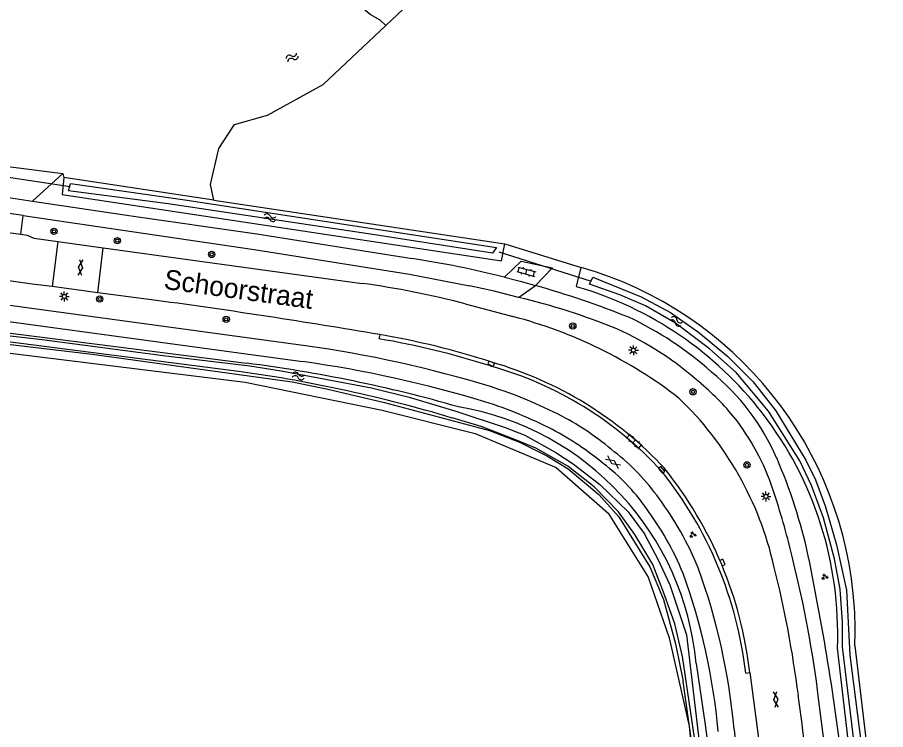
# Model space of a CAD drawing. Extents: x 134297 to 137000, y 403500 to 406000.
# Drawn here: x 136614.5 to 136724.4, y 404031.9 to 404122.1 of the extents above; entities that cross this region are included whole.
import ezdxf

# ---------------------------------------------------------------- set-up
doc = ezdxf.new("R2010")
doc.units = 0
for name, color, linetype in [('gg-anno-openbare ruimte label', 7, 'Continuous'), ('gg-knt-bronhoudergrens', 7, 'Continuous'), ('gg-knt-verharding', 7, 'Continuous'), ('gg-kntw-bovenkant insteek waterloop', 7, 'Continuous'), ('gg-kntw-waterlijn', 7, 'Continuous'), ('gg-kwrk-duiker nz buis', 7, 'Continuous'), ('gt-grn-groengrens', 7, 'Continuous'), ('gt-grn-weggrens', 7, 'Continuous'), ('gt-symb-boom', 7, 'Continuous'), ('gt-symb-gesloten verharding', 7, 'Continuous'), ('gt-symb-groenvak', 7, 'Continuous'), ('gt-symb-klinker verharding', 7, 'Continuous'), ('gt-symb-kolk', 7, 'Continuous'), ('gt-symb-lichtmast', 7, 'Continuous'), ('gt-symb-watersymbool', 7, 'Continuous')]:
    doc.layers.add(name, color=color, linetype=linetype)

# ---------------------------------------------------------------- blocks, each defined once
blk = doc.blocks.new('gt0-BOOM')
at = {"layer": 'gt-symb-boom'}
for radius in [0.4, 0.2]:
    blk.add_circle((0, 0), radius, dxfattribs=at)
blk = doc.blocks.new('gt0-LMAST')
at = {"layer": 'gt-symb-lichtmast'}
for p, q in [((-0.18, 0.17), (-0.45, 0.44)), ((-0.01, 0.25), (-0.01, 0.62)), ((0.17, 0.17), (0.44, 0.44)), ((-0.26, 0), (-0.63, 0)), ((-0.18, -0.18), (-0.45, -0.45)), ((-0.01, -0.25), (-0.01, -0.63)), ((0.44, -0.45), (0.17, -0.18)), ((0.24, 0), (0.62, 0))]:
    blk.add_line(p, q, dxfattribs=at)
blk.add_circle((-0.01, 0), 0.25, dxfattribs=at)
blk = doc.blocks.new('gt0-GRVAK')
at = {"layer": 'gt-symb-groenvak'}
for p, q in [((-0.11, 0.19), (-0.23, 0.24)), ((-0.18, 0.15), (0.09, 0.15)), ((-0.09, 0.21), (-0.16, 0.32)), ((-0.05, 0.21), (-0.05, 0.39)), ((0, 0.21), (0.06, 0.32)), ((0.01, 0.19), (0.13, 0.24)), ((0.26, -0.05), (0.2, 0.06)), ((0.3, -0.05), (0.3, 0.13)), ((0.35, -0.05), (0.41, 0.06)), ((-0.24, -0.23), (-0.36, -0.18)), ((-0.32, -0.26), (-0.05, -0.26)), ((-0.23, -0.21), (-0.29, -0.09)), ((-0.18, -0.2), (-0.18, -0.02)), ((-0.14, -0.21), (-0.07, -0.09)), ((-0.12, -0.23), (0, -0.18)), ((0.24, -0.07), (0.12, -0.02)), ((0.17, -0.11), (0.44, -0.11)), ((0.37, -0.07), (0.49, -0.02))]:
    blk.add_line(p, q, dxfattribs=at)
blk = doc.blocks.new('gt0-GESVH1')
at = {"layer": 'gt-symb-gesloten verharding'}
for p, q in [((-0.99, -0.26), (0.01, 0.24)), ((0.01, -0.26), (-0.99, 0.24)), ((0.01, 0.24), (1.01, -0.26)), ((1.01, 0.24), (0.01, -0.26))]:
    blk.add_line(p, q, dxfattribs=at)
blk = doc.blocks.new('gt0-KOLK')
at = {"layer": 'gt-symb-kolk'}
blk.add_lwpolyline([(0, 0), (0.38, 0), (0.38, 0.4), (-0.38, 0.4), (-0.38, 0), (0, 0)], dxfattribs=at)
blk = doc.blocks.new('gt0-WA')
at = {"layer": 'gt-symb-watersymbool'}
for centre, start, end in [((-0.32, 0.02), 28.0725, 151.9275), ((0.43, 0.42), 208.0725, 331.9275), ((-0.32, -0.43), 28.0725, 151.9275), ((0.43, -0.03), 208.0725, 331.9275)]:
    blk.add_arc(centre, 0.425, start, end, dxfattribs=at)
blk = doc.blocks.new('gt0-KL1')
at = {"layer": 'gt-symb-klinker verharding'}
for p, q in [((-1.15, 0.3), (1.15, 0.3)), ((-1, -0.3), (-1, 0.3)), ((-0.5, 0.3), (-0.5, 0.45)), ((0, -0.3), (0, 0.3)), ((0.5, 0.3), (0.5, 0.45)), ((1, -0.3), (1, 0.3)), ((-1.15, -0.3), (1.15, -0.3)), ((-0.5, -0.45), (-0.5, -0.3)), ((0.5, -0.45), (0.5, -0.3))]:
    blk.add_line(p, q, dxfattribs=at)

msp = doc.modelspace()

# ---------------------------------------------------------------- linework, layer by layer
at = {"layer": 'gg-knt-bronhoudergrens'}
msp.add_line((136661.12, 404121.02), (136664.77, 404124.47), dxfattribs=at)
for points in [[(136661.12, 404121.02), (136660.4, 404121.69), (136659.13, 404122.43), (136657.01, 404124.23), (136651.93, 404126.77), (136645.8, 404133.12), (136643.89, 404137.78), (136643.04, 404141.91), (136642.75, 404143.92), (136636.98, 404147.84)], [(136639.37, 404098.93), (136638.96, 404100.89), (136640.02, 404105.44), (136641.98, 404108.51), (136646.16, 404109.67), (136653.2, 404113.54), (136661.12, 404121.02)], [(136565.32, 404088.32), (136600.22, 404081.2), (136643.34, 404075.89), (136660.67, 404072.34), (136672.43, 404069.38), (136682.66, 404065.06), (136689.26, 404059.31), (136694.33, 404051.19), (136696.95, 404043.5), (136699.49, 404032.34), (136701.69, 404009.21), (136701.34, 404009.21)]]:
    msp.add_lwpolyline(points, dxfattribs=at)
at = {"layer": 'gg-knt-verharding'}
for p, q in [((136607.31, 404103.94), (136620.25, 404102.31)), ((136616.42, 404098.79), (136620.25, 404102.31)), ((136606.78, 404100.22), (136616.42, 404098.79)), ((136615.26, 404096.96), (136606.36, 404098.26)), ((136614.95, 404094.6), (136615.26, 404096.96)), ((136606.02, 404095.78), (136614.95, 404094.6)), ((136619.62, 404093.68), (136618.9, 404087.97)), ((136619.62, 404093.68), (136625.35, 404092.89)), ((136624.7, 404087.2), (136625.35, 404092.89)), ((136625.35, 404092.89), (136658.13, 404088.38)), ((136650.95, 404080.49), (136599.45, 404087.49)), ((136624.7, 404087.2), (136618.9, 404087.97)), ((136632.12, 404086.22), (136624.7, 404087.2)), ((136660.36, 404081.89), (136660.25, 404081.38)), ((136706.66, 404039.06), (136707.17, 404039.13)), ((136705.19, 404031.9), (136709.48, 403985.12))]:
    msp.add_line(p, q, dxfattribs=at)
for points in [[(136616.42, 404098.79), (136628.91, 404096.94), (136644.81, 404094.67), (136664.47, 404091.53)], [(136615.26, 404096.96), (136644.46, 404092.68), (136664.1, 404089.55), (136671.71, 404088.08)], [(136614.95, 404094.6), (136615.77, 404094.5), (136616.61, 404094.1), (136619.62, 404093.68)], [(136618.9, 404087.97), (136616.39, 404088.3), (136603.65, 404090.09), (136593.07, 404091.67)], [(136676.14, 404089.17), (136678.24, 404091.18), (136682.19, 404090.34), (136680.05, 404088.12)], [(136578.66, 404089.05), (136588.33, 404087.2), (136599.16, 404085.49), (136650.59, 404078.48)], [(136676.14, 404089.17), (136678.1, 404088.66), (136680.05, 404088.12)], [(136677.91, 404086.61), (136674.82, 404087.39), (136671.71, 404088.08)], [(136671.16, 404085.78), (136674.18, 404085), (136677.19, 404084.18)], [(136707.17, 404039.13), (136708.17, 404031.47), (136709.02, 404023.8), (136710.15, 404011.91), (136711.12, 404000), (136711.34, 403997.04), (136711.41, 403995.52)], [(136718.71, 404007.42), (136717.17, 404024.79), (136716.57, 404030.31), (136715.87, 404035.83)]]:
    msp.add_lwpolyline(points, dxfattribs=at)
for centre, radius, start, end in [((136645.52, 403967.49), 125.47, 75.8773, 81.316), ((136642.21, 403974.69), 114.81, 75.3963, 82.0295), ((136645.54, 403967.48), 125.48, 68.3367, 74.0353), ((136658.88, 404005.82), 83, 67.7322, 76.7429), ((136522.97, 403280.07), 813.51, 80.2772, 82.28963), ((136662.32, 404027.32), 58.78, 52.3757, 75.3438), ((136673.23, 404044.58), 43.69, 48.2119, 64.7543), ((136644.19, 403985.87), 97.38, 71.8546, 80.4427), ((136672.84, 404044.1), 42.32, 48.2153, 65.5904), ((136643.08, 403980.31), 102.51, 72.2302, 80.3591), ((136630.2, 403930.91), 151.01, 72.9899, 82.1027), ((136630.08, 403930.44), 149.45, 73.0472, 82.1136), ((136661.89, 404033.35), 46.29, 42.492, 74.3556), ((136661.3, 404032.4), 47.87, 42.8297, 73.967), ((136684.09, 404054.8), 28.86, 23.4717, 50.7778), ((136656.57, 404019.58), 58.51, 62.7099, 72.2815), ((136680.36, 404051.21), 32.02, 38.1141, 49.7819), ((136656.67, 404020), 56.04, 62.8878, 72.3466), ((136668.84, 404043.25), 42.42, 12.7332, 46.2021), ((136665.8, 404038.57), 37.41, 49.6417, 61.9392), ((136680.55, 404052.34), 31.18, 17.4794, 36.6898), ((136665.1, 404037.38), 36.73, 50.1476, 62.2423), ((136673.38, 404045.5), 27.25, 35.0376, 52.3544), ((136673.69, 404045.77), 24.81, 35.045, 52.9511), ((136648.83, 404039.52), 67.29, 12.346, 23.4403), ((136656.86, 404033.34), 50.12, 6.5491, 38.6178), ((136657.31, 404033.48), 50.17, 6.4574, 38.8239), ((136663.58, 404037.22), 40.04, 22.2628, 36.6825), ((136628.27, 404034.28), 86.48, 12.8031, 18.4856), ((136664.06, 404037.53), 37.44, 22.1532, 36.9064), ((136571.75, 404018.2), 145.2, 6.9716, 14.0482), ((136376.88, 403984.88), 344.67, 6.676, 11.553), ((136624.01, 404024.62), 81.5, 5.1267, 19.9256), ((136571.63, 404017.99), 142.85, 7.3457, 14.0202), ((136621.92, 404024.12), 81.61, 5.3152, 19.7199), ((136075.65, 403952.45), 643.14, 4.88308, 7.48781)]:
    msp.add_arc(centre, radius, start, end, dxfattribs=at)
at = {"layer": 'gg-kntw-bovenkant insteek waterloop'}
for p, q in [((136639.37, 404098.93), (136620.4, 404101.8)), ((136639.37, 404098.93), (136676.16, 404093.37)), ((136685.24, 404087.97), (136685.85, 404090.41)), ((136598.99, 404083.97), (136643.49, 404078.28))]:
    msp.add_line(p, q, dxfattribs=at)
for points in [[(136620.4, 404101.8), (136620.19, 404099.64), (136675.74, 404091.22), (136676.16, 404093.37)], [(136565.22, 404089.23), (136571.29, 404087.63), (136581.09, 404085.35), (136586.26, 404084.37), (136593.96, 404083.11), (136601.51, 404082.09), (136623.96, 404079.43), (136649.28, 404075.92), (136653.62, 404075.02), (136660.97, 404073.3), (136674.23, 404069.75), (136678.05, 404068.29), (136681.58, 404066.52), (136684.2, 404064.93), (136688.06, 404061.66), (136690.6, 404058.85), (136694.53, 404052.51), (136696.26, 404048.36), (136697.76, 404042.75), (136698.75, 404038.01)], [(136720.45, 404042.49), (136722.46, 404025.43), (136723.74, 404013.87)], [(136724.35, 404008.35), (136722.15, 404008.09), (136720.26, 404025.16), (136718.26, 404042.23)], [(136700.37, 404040.28), (136701.52, 404032.49), (136702.53, 404024.69), (136703.69, 404012.35), (136704.77, 404000)], [(136702.66, 403999.96), (136701.81, 404009.69), (136700.75, 404021.18), (136699.83, 404030.17), (136698.75, 404038.01)]]:
    msp.add_lwpolyline(points, dxfattribs=at)
for centre, radius, start, end in [((136672.56, 404044.36), 47.93, 3.4685, 73.8961), ((136672.54, 404044.01), 45.75, 37.659, 73.8804), ((136620.6, 403899.28), 180.46, 74.0068, 82.7147), ((136664.25, 404037), 36.27, 5.1881, 80.3547), ((136672.54, 404044.02), 45.75, 357.7552, 37.6557), ((136673.1, 404044.36), 47.39, 357.7421, 3.5079)]:
    msp.add_arc(centre, radius, start, end, dxfattribs=at)
at = {"layer": 'gg-kntw-waterlijn'}
msp.add_line((136642.83, 404077.2), (136598.33, 404082.89), dxfattribs=at)
for points in [[(136621.22, 404101.03), (136635.68, 404098.98), (136675.12, 404092.93), (136674.62, 404092.22), (136659.74, 404094.55), (136633.59, 404098.45), (136620.98, 404100.12), (136621.22, 404101.03)], [(136721.97, 404017), (136718.9, 404042.38), (136718.91, 404045.51), (136718.61, 404049.68), (136717.89, 404053.51), (136716.47, 404058.69), (136714.97, 404062.79), (136713.5, 404065.91), (136709.54, 404072.23), (136705.46, 404077.12), (136702.05, 404080.11), (136697.76, 404083.36), (136693.96, 404085.54), (136690.74, 404086.93), (136686.89, 404088.29), (136687.32, 404089.16)], [(136687.32, 404089.16), (136693.41, 404086.68), (136697.12, 404084.72), (136700.67, 404082.22), (136704.38, 404079.11), (136707.61, 404075.94), (136710.46, 404072.25), (136714.24, 404066.02), (136715.46, 404063.51), (136716.73, 404060.12), (136718.15, 404055.29), (136719.4, 404049.57), (136719.84, 404041.34), (136722.45, 404020.85)], [(136597.8, 404083.57), (136617.64, 404081.29), (136632.96, 404079.27), (136643.91, 404077.93), (136647.89, 404077.32), (136659.32, 404075.17), (136664.07, 404073.98), (136669.99, 404072.2), (136676.22, 404070.13), (136678.71, 404069.18), (136682.62, 404066.98), (136684.84, 404065.54), (136688.19, 404062.94), (136691.77, 404059.48), (136693.79, 404056.74), (136695.55, 404053.46), (136697.06, 404050.22), (136699.17, 404043.92), (136702.93, 404012.17)], [(136700.71, 404027.21), (136698.65, 404041.14), (136697.68, 404045.3), (136696.39, 404048.96), (136694.89, 404052.79), (136692.64, 404056.59), (136690.56, 404059.45), (136687.48, 404062.63), (136684.16, 404065.23), (136680.09, 404067.52), (136677.65, 404068.56), (136673.17, 404070.25), (136669.53, 404071.35)]]:
    msp.add_lwpolyline(points, dxfattribs=at)
msp.add_arc((136617.71, 403898.91), 180.05, 73.2739, 81.9809, dxfattribs=at)
at = {"layer": 'gg-kwrk-duiker nz buis'}
for p, q in [((136621.19, 404100.59), (136604.33, 404103.17)), ((136675.44, 404092.37), (136687.1, 404088.68))]:
    msp.add_line(p, q, dxfattribs=at)
at = {"layer": 'gt-grn-groengrens'}
for p, q in [((136620.25, 404102.31), (136620.4, 404101.8)), ((136676.16, 404093.37), (136685.85, 404090.41))]:
    msp.add_line(p, q, dxfattribs=at)
at = {"layer": 'gt-grn-weggrens'}
msp.add_line((136677.91, 404086.61), (136680.05, 404088.12), dxfattribs=at)

# ---------------------------------------------------------------- block references
at = {"layer": 'gt-symb-boom'}
for p in [(136619.15, 404094.98), (136627.17, 404093.79), (136639.1, 404092.05), (136624.93, 404086.41), (136640.93, 404083.83), (136684.78, 404082.98), (136699.98, 404074.66), (136706.82, 404065.41)]:
    msp.add_blockref('gt0-BOOM', p, dxfattribs=at)
at = {"layer": 'gt-symb-gesloten verharding'}
for p, rotation in [((136622.52, 404090.4), -95.91007032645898), ((136689.86, 404065.75), 143.98947460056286), ((136710.47, 404035.73), -83.96999119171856)]:
    msp.add_blockref('gt0-GESVH1', p, dxfattribs=dict(at, rotation=rotation))
at = {"layer": 'gt-symb-groenvak'}
for p in [(136699.95, 404056.57), (136716.64, 404051.23)]:
    msp.add_blockref('gt0-GRVAK', p, dxfattribs=at)
at = {"layer": 'gt-symb-klinker verharding'}
for p, rotation in [((136678.9, 404089.86), -15.134475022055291), ((136692.53, 404068.37), -41.43377070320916)]:
    msp.add_blockref('gt0-KL1', p, dxfattribs=dict(at, rotation=rotation))
at = {"layer": 'gt-symb-kolk'}
for p, rotation in [((136674.52, 404078.4), 156.305028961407), ((136695.86, 404064.67), -49.98904227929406), ((136703.54, 404052.98), -67.10240897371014)]:
    msp.add_blockref('gt0-KOLK', p, dxfattribs=dict(at, rotation=rotation))
at = {"layer": 'gt-symb-lichtmast'}
for p in [(136620.46, 404086.73), (136692.45, 404079.92), (136709.22, 404061.42)]:
    msp.add_blockref('gt0-LMAST', p, dxfattribs=at)
at = {"layer": 'gt-symb-watersymbool'}
for p, rotation in [((136649.23, 404116.97), 27.641142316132), ((136646.52, 404096.7), 175.00791883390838), ((136697.9, 404083.54), 155.9968097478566), ((136650.11, 404076.66), 175.00791883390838)]:
    msp.add_blockref('gt0-WA', p, dxfattribs=dict(at, rotation=rotation))

# ---------------------------------------------------------------- texts
at = {"layer": 'gg-anno-openbare ruimte label'}
msp.add_text('Schoorstraat', height=2.5, rotation=352.2, dxfattribs=at).set_placement((136632.95, 404087.71))

doc.saveas('drawing.dxf')
